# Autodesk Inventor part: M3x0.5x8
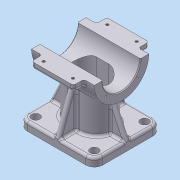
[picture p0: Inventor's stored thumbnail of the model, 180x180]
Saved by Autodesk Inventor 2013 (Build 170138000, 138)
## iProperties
Company: 한국ATC센터
Created: 2009-02
Part Number: M3x0.5x8
Document SubType Name: Modeling
Designer: KYOUNG IL JANG
Density: 2.71 g/cm^3
Material: 알루미늄-6061
Vendor: CBT Solutions
Mass: 478.987 g
Surface Area: 471.043 cm^2
Volume: 176.748 cm^3
Author: KYOUNG IL JANG
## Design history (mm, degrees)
sketch "스케치1"
  geometry: L1 (-45, 40)-(45, 40); L2 (45, 40)-(45, -40); L3 (45, -40)-(-45, -40); L4 (-45, -40)-(-45, 40); 3 further points
  constraints: 8 end point, 2 midpoint, 2 parallel, 1 horizontal, 1 horizontal alignment, 1 perpendicular, 1 vertical alignment
  dimensions: "d0" = 90 distance of L2.end L3.end; "d1" = 80 distance of L1.end L2.end
extrude "돌출1" new body sketch "스케치1" distance "d2" = 10; taper "d3" = 0 deg
sketch "스케치2"
  geometry: L1 (40, 0)-(-40, 0) reference; C1 r 32.5 at (0, 80); 2 further points
  constraints: 1 centre point, 1 midpoint, 1 vertical alignment
  dimensions: "d4" = 65 diameter of C1; "d5" = 80 distance from line of C1.centre L1
extrude "돌출2" join sketch "스케치2" stored distance "d6" = 75; taper "d7" = 0 deg
sketch "스케치3"
  geometry: L1 (-7.5, -20)-(7.5, -20); L2 (7.5, 20)-(-7.5, 20); A1 r 20 centre (7.5, 0) between (7.5, -20) and (7.5, 20); A2 r 20 centre (-7.5, 0) between (-7.5, 20) and (-7.5, -20); 2 further points
  constraints: 4 end point, 4 point on circle, 4 tangent, 2 centre point, 1 horizontal, 1 horizontal alignment, 1 midpoint, 1 parallel, 1 vertical alignment
  dimensions: "d8" = 20 radius of A2; "d9" = 55 dimension on A1 A2
extrude "돌출3" join sketch "스케치3" stored distance "d10" = 75; taper "d11" = 0 deg
fillet "모깎기1" dims "d12" = 10
sketch "스케치4"
  geometry: L1 (-45, 0)-(-45, 10) reference; L2 (37.5, 47.5)-(-37.5, 47.5) reference; L3 (-45, 10)-(-27.513, 47.5); 1 further point
  constraints: 2 end point, 1 point on line
  dimensions: "d13" = 25 deg angle of L3 L1
sketch "스케치5"
  geometry: L1 (-40, 0)-(-40, 10) reference; L2 (-40, 10)-(-22.912, 56.95); 2 further points
  constraints: 2 end point, 2 other
  dimensions: "d14" = 20 deg angle of L2 L1
feature "리브1" dims "d15" = 1, "d16" = 6, "d17" = 0
feature "리브2" dims "d18" = 1, "d19" = 6, "d20" = 0
fillet "모깎기2" dims "d21" = 3
fillet "모깎기3" dims "d22" = 3
fillet "모깎기4" dims "d23" = 3
fillet "모깎기5" dims "d24" = 3
fillet "모깎기6" dims "d25" = 3
fillet "모깎기7" dims "d26" = 3
fillet "모깎기8" dims "d27" = 3
sketch "스케치6"
  geometry: A1 r 10 centre (35, -30) between (35, -40) and (45, -30) reference; 1 further point
hole "구멍1" sketch "스케치6" at (35, -30) diameter "d28" = 10; stored, may be unused: countersink angle "d32" = 90 deg, drill point angle "d34" = 118 deg; dims "d29" = 6, "d30" = 4, "d31" = 2, "d33" = 8
hole "구멍2" diameter "d37" = 45; stored, may be unused: countersink angle "d41" = 90 deg, drill point angle "d43" = 118 deg; dims "d35" = 10, "d36" = 10, "d38" = 6, "d39" = 4, "d40" = 2, "d42" = 8
sketch "스케치7"
  geometry: C1 r 22.5 at (0, 0) reference; 2 further points
  dimensions: "d44" = 135 deg dimension on C1.centre point (-18.738, 18.738) point (80, 0); "d45" = 26.5 distance of point (-18.738, 18.738) C1.centre
hole "구멍3" sketch "스케치7" at (-18.738, 18.738) diameter "d46" = 2.459; stored, may be unused: countersink angle "d50" = 90 deg, drill point angle "d52" = 118 deg; dims "d47" = 8, "d48" = 4, "d49" = 2, "d51" = 10
node "작업 평면1"
sketch "스케치8"
  geometry: C1 r 10 at (0, 0); 1 further point
  constraints: 1 centre point, 1 coincident
  dimensions: "d57" = 20 diameter of C1
extrude "돌출4" join sketch "스케치8" stored distance "d58" = 75; taper "d59" = 0 deg
hole "구멍4" diameter "d62" = 8.376; stored, may be unused: countersink angle "d66" = 90 deg, drill point angle "d68" = 118 deg; dims "d60" = 10, "d61" = 10, "d63" = 7, "d64" = 4, "d65" = 2, "d67" = 10
chamfer "모따기1" distance "d69" = 1; stored, may be unused: second distance "d70" = 2, angle "d71" = 45 deg
fillet "모깎기9" dims "d72" = 3
sketch "스케치9"
  geometry: L1 (-31.623, 87.5)-(-45, 87.5); L2 (-45, 87.5)-(-45, 72.5); L3 (-45, 72.5)-(-31.623, 72.5); A1 r 32.5 centre (0, 80) between (-31.623, 87.5) and (-31.623, 72.5) reference; 1 further point
  constraints: 6 end point, 2 parallel, 2 point on circle, 1 horizontal, 1 perpendicular
  dimensions: "d73" = 15 distance of L1.end L2.end; "d74" = 45 distance from line of A1.centre L2
extrude "돌출5" join sketch "스케치9" stored distance "d75" = 50; taper "d76" = 0 deg
fillet "모깎기10" dims "d77" = 3
fillet "모깎기11" dims "d78" = 3
sketch "스케치10"
  geometry: L1 (-61.625, 62.366)-(0, 62.366); L2 (0, 62.366)-(0, -62.366); L3 (0, -62.366)-(-61.625, -62.366); L4 (-61.625, -62.366)-(-61.625, 62.366); C1 r 32.5 at (0, 0) reference; 2 further points
  constraints: 8 end point, 2 parallel, 1 coincident, 1 horizontal, 1 midpoint, 1 perpendicular
extrude "돌출6" cut sketch "스케치10" stored distance "d79" = 10; taper "d80" = 0 deg
node "작업 평면2"
sketch "스케치11"
  geometry: L1 (-7.5, -15)-(7.5, -15); L2 (7.5, 15)-(-7.5, 15); A1 r 20 centre (-7.5, 0) between (-7.5, 20) and (-26.807, 5.217) reference; A2 r 20 centre (7.5, 0) between (26.807, 5.217) and (7.5, 20) reference; A3 r 15 centre (7.5, 0) between (7.5, -15) and (7.5, 15); A4 r 15 centre (-7.5, 0) between (-7.5, 15) and (-7.5, -15); 1 further point
  constraints: 4 end point, 4 point on circle, 3 tangent, 2 centre point, 2 coincident, 1 horizontal, 1 parallel
  dimensions: "d82" = 15 radius of A4
extrude "돌출7" cut sketch "스케치11" stored distance "d83" = 10; taper "d84" = 0 deg
sketch "스케치12"
  geometry: 1 further point
hole "구멍5" sketch "스케치12" at (0, 0) diameter "d85" = 12; stored, may be unused: countersink angle "d89" = 90 deg, drill point angle "d91" = 118 deg; dims "d86" = 6, "d87" = 38, "d88" = 10, "d90" = 8
sketch "스케치13"
  geometry: L1 (-15.5, -12.5)-(-59.5, -12.5) reference; 3 further points
  constraints: 1 horizontal alignment
  dimensions: "d92" = 35 distance of point (-20, -5.5) point (-55, -5.5); "d93" = 17.5 horizontal distance of point (-37.5, 32.5) point (-55, -5.5) (= 0.5 x d92); "d94" = 7 distance from line of L1 point (-55, -5.5)
hole "구멍6" sketch "스케치13" at (-55, -5.5), (-20, -5.5) diameter "d95" = 3.242; stored, may be unused: countersink angle "d99" = 90 deg, drill point angle "d101" = 118 deg; dims "d96" = 6, "d97" = 38, "d98" = 10, "d100" = 8
sketch "스케치14"
  geometry: C1 r 10 at (0, 0); 1 further point
  constraints: 1 centre point, 1 coincident
  dimensions: "d102" = 20 diameter of C1
extrude "돌출8" cut sketch "스케치14" distance "d103" = 5; taper "d104" = 0 deg
node "솔리드1"
mirror "대칭1"
mirror "대칭2"
mirror "대칭3"
mirror "대칭4"
pattern_circular "원형 패턴1" dims angle "d54" = 360 deg
mirror "대칭5"
mirror "대칭6"
mirror "대칭7"
other parameters: "d56" = -117
